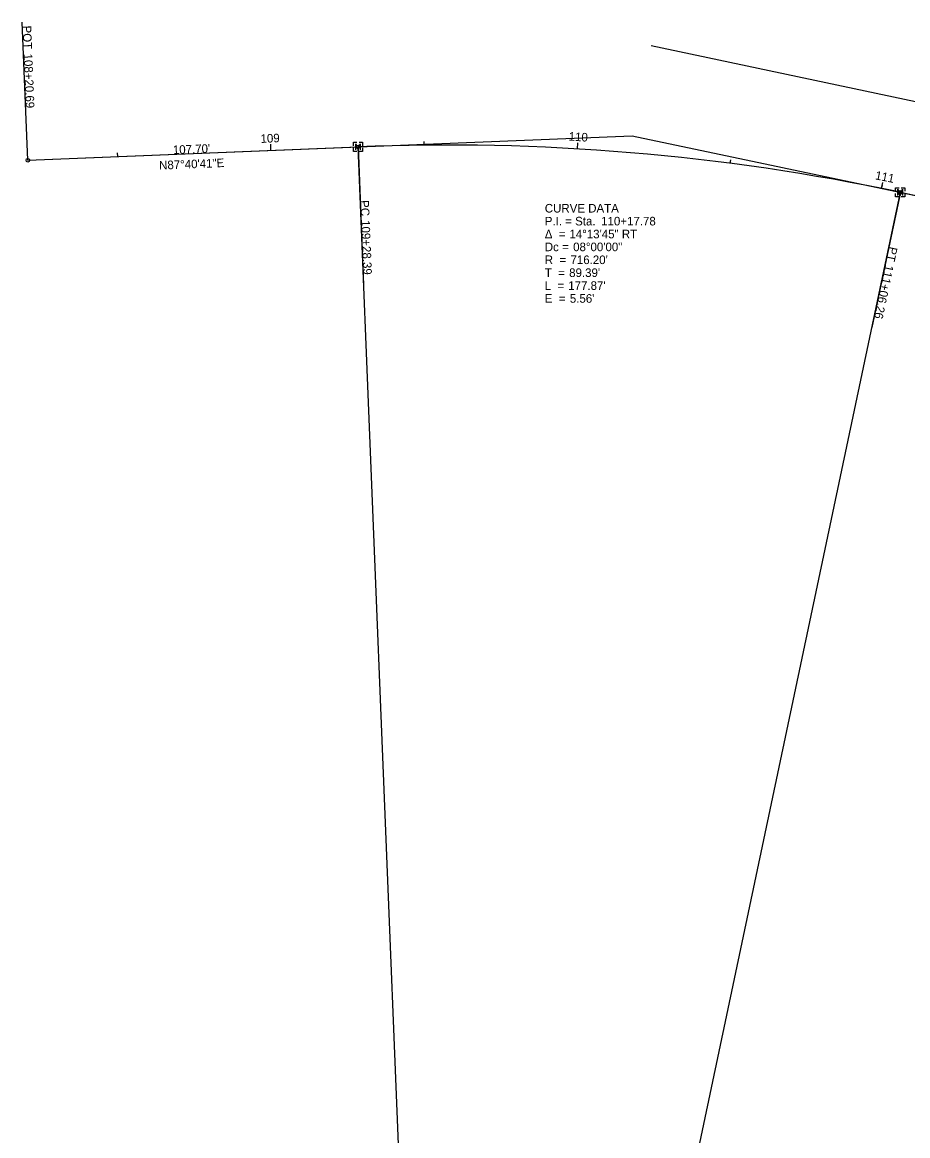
# Model space of a CAD drawing. Extents: x 2003596 to 2006888, y 571866 to 574416.
# Drawn here: x 2003595.8 to 2003884.4, y 572619.8 to 572982.7 of the extents above; entities that cross this region are included whole.
import ezdxf

# ---------------------------------------------------------------- set-up
doc = ezdxf.new("R2010")
doc.units = 0
for name, color, linetype in [('GE_X_Alignment', 7, 'Continuous'), ('GE_X_Alignment_1000_Bearings', 7, 'Continuous'), ('GE_X_Alignment_1000_Cardinal_Points', 7, 'Continuous'), ('GE_X_Alignment_1000_Curve_Data', 7, 'Continuous'), ('GE_X_Alignment_1000_Distances', 7, 'Continuous'), ('GE_X_Alignment_1000_Stations', 7, 'Continuous'), ('GE_X_Alignment_100_Bearings', 7, 'Continuous'), ('GE_X_Alignment_100_Cardinal_Points', 7, 'Continuous'), ('GE_X_Alignment_100_Curve_Data', 7, 'Continuous'), ('GE_X_Alignment_100_Distances', 7, 'Continuous'), ('GE_X_Alignment_100_Stations', 7, 'Continuous'), ('GE_X_Alignment_500_Bearings', 7, 'Continuous'), ('GE_X_Alignment_500_Cardinal_Points', 7, 'Continuous'), ('GE_X_Alignment_500_Curve_Data', 7, 'Continuous'), ('GE_X_Alignment_500_Distances', 7, 'Continuous'), ('GE_X_Alignment_500_Stations', 7, 'Continuous'), ('RW_X_Esmt_SH', 7, 'Continuous'), ('SC_Scratch1', 7, 'Continuous'), ('SV_X_Mon_Cells_Found', 7, 'Continuous'), ('SV_X_Random_Point', 7, 'Continuous')]:
    doc.layers.add(name, color=color, linetype=linetype)

msp = doc.modelspace()

# ---------------------------------------------------------------- linework, layer by layer
at = {"layer": 'GE_X_Alignment'}
for p, q in [((2003597.61, 572937.73), (2003705.22, 572942.09)), ((2003882.01, 572927.27), (2004086.95, 572884.06))]:
    msp.add_line(p, q, dxfattribs=at)
msp.add_arc((2003734.24, 572226.48), 716.2, 78.09264, 92.32181, dxfattribs=at)
at = {"layer": 'GE_X_Alignment_1000_Cardinal_Points'}
for p, q in [((2003597.61, 572937.73), (2003595.79, 572982.69)), ((2003705.22, 572942.09), (2003707.04, 572897.13)), ((2003882.01, 572927.27), (2003872.72, 572883.24))]:
    msp.add_line(p, q, dxfattribs=at)
for centre in [(2003705.22, 572942.09), (2003597.61, 572937.73), (2003882.01, 572927.27)]:
    msp.add_circle(centre, 0.6, dxfattribs=at)
at = {"layer": 'GE_X_Alignment_1000_Stations'}
msp.add_line((2003776.8, 572941.42), (2003776.92, 572943.41), dxfattribs=at)
at = {"layer": 'GE_X_Alignment_100_Cardinal_Points'}
for p, q in [((2003597.61, 572937.73), (2003595.79, 572982.69)), ((2003705.22, 572942.09), (2003707.04, 572897.13)), ((2003882.01, 572927.27), (2003872.72, 572883.24))]:
    msp.add_line(p, q, dxfattribs=at)
for centre in [(2003705.22, 572942.09), (2003597.61, 572937.73), (2003882.01, 572927.27)]:
    msp.add_circle(centre, 0.6, dxfattribs=at)
at = {"layer": 'GE_X_Alignment_100_Stations'}
for p, q in [((2003676.85, 572940.94), (2003676.77, 572942.94)), ((2003726.82, 572942.64), (2003726.81, 572943.84)), ((2003776.8, 572941.42), (2003776.92, 572943.41)), ((2003626.89, 572938.92), (2003626.85, 572940.12)), ((2003826.56, 572936.71), (2003826.72, 572937.9)), ((2003875.88, 572928.54), (2003876.28, 572930.5))]:
    msp.add_line(p, q, dxfattribs=at)
at = {"layer": 'GE_X_Alignment_500_Cardinal_Points'}
for p, q in [((2003597.61, 572937.73), (2003595.79, 572982.69)), ((2003705.22, 572942.09), (2003707.04, 572897.13)), ((2003882.01, 572927.27), (2003872.72, 572883.24))]:
    msp.add_line(p, q, dxfattribs=at)
for centre in [(2003705.22, 572942.09), (2003597.61, 572937.73), (2003882.01, 572927.27)]:
    msp.add_circle(centre, 0.6, dxfattribs=at)
at = {"layer": 'GE_X_Alignment_500_Stations'}
for p, q in [((2003776.8, 572941.42), (2003776.92, 572943.41)), ((2003676.85, 572940.94), (2003676.8, 572942.14)), ((2003875.88, 572928.54), (2003876.12, 572929.71))]:
    msp.add_line(p, q, dxfattribs=at)
at = {"layer": 'RW_X_Esmt_SH'}
msp.add_line((2003800.73, 572975.07), (2004225.49, 572885.5), dxfattribs=at)
at = {"layer": 'SC_Scratch1'}
for p, q in [((2003597.61, 572937.73), (2003794.54, 572945.72)), ((2003794.54, 572945.72), (2004215.36, 572856.98)), ((2003734.24, 572226.48), (2003705.22, 572942.09)), ((2003734.24, 572226.48), (2003882.01, 572927.27))]:
    msp.add_line(p, q, dxfattribs=at)
at = {"layer": 'SV_X_Mon_Cells_Found'}
for p, q in [((2003705.22, 572942.09), (2003705.22, 572942.09)), ((2003881.94, 572927.28), (2003881.94, 572927.28))]:
    msp.add_line(p, q, dxfattribs=at)
for points in [[(2003703.72, 572942.47), (2003703.72, 572943.6), (2003704.84, 572943.6)], [(2003704.48, 572941.09), (2003704.48, 572943.09), (2003705.22, 572941.09), (2003705.96, 572943.09), (2003705.96, 572941.09)], [(2003705.58, 572943.6), (2003706.72, 572943.6), (2003706.72, 572942.47)], [(2003704.84, 572940.59), (2003703.72, 572940.59), (2003703.72, 572941.72)], [(2003706.72, 572941.72), (2003706.72, 572940.59), (2003705.58, 572940.59)], [(2003880.44, 572927.66), (2003880.44, 572928.78), (2003881.56, 572928.78)], [(2003882.3, 572928.78), (2003883.44, 572928.78), (2003883.44, 572927.66)], [(2003881.56, 572925.78), (2003880.44, 572925.78), (2003880.44, 572926.9)], [(2003881.2, 572926.28), (2003881.2, 572928.28), (2003881.94, 572926.28), (2003882.68, 572928.28), (2003882.68, 572926.28)], [(2003883.44, 572926.9), (2003883.44, 572925.78), (2003882.3, 572925.78)]]:
    msp.add_lwpolyline(points, dxfattribs=at)
at = {"layer": 'SV_X_Random_Point'}
for p, q in [((2003881.34, 572926.6), (2003882.68, 572927.94)), ((2003881.34, 572927.94), (2003882.68, 572926.6))]:
    msp.add_line(p, q, dxfattribs=at)

# ---------------------------------------------------------------- texts
at = {"layer": 'GE_X_Alignment_1000_Bearings'}
msp.add_text('N87°40\'41"E', height=2.8, rotation=2.3218, dxfattribs=at).set_placement((2003640.44, 572934.66))
at = {"layer": 'GE_X_Alignment_1000_Cardinal_Points'}
for s, rotation, p in [('POT', 272.3218, (2003595.88, 572981.55)), ('108+20.69', 272.3218, (2003596.25, 572972.43)), ('PC', 272.3218, (2003705.97, 572924.66)), ('109+28.39', 272.3218, (2003706.24, 572918.14)), ('PT', 258.0925, (2003878.36, 572909.72)), ('111+06.26', 258.0925, (2003877.1, 572903.76))]:
    msp.add_text(s, height=2.8, rotation=rotation, dxfattribs=at).set_placement(p)
at = {"layer": 'GE_X_Alignment_1000_Curve_Data'}
for s, p in [('CURVE DATA', (2003766.1, 572920.68)), ('P.I. = Sta. ', (2003766.1, 572916.48)), ('110+17.78', (2003784.47, 572916.48)), ('Δ  = ', (2003766.1, 572912.28)), ('14°13\'45" RT', (2003774.13, 572912.28)), ('Dc = ', (2003766.1, 572908.08)), ('08°00\'00"', (2003775.34, 572908.08)), ('R  = ', (2003766.1, 572903.88)), ("716.20'", (2003774.47, 572903.88)), ('T  = ', (2003766.1, 572899.68)), ("89.39'", (2003774.04, 572899.68)), ('L  = ', (2003766.1, 572895.48)), ("177.87'", (2003773.75, 572895.48)), ('E  = ', (2003766.1, 572891.28)), ("5.56'", (2003774.26, 572891.28))]:
    msp.add_text(s, height=2.8, dxfattribs=at).set_placement(p)
at = {"layer": 'GE_X_Alignment_1000_Distances'}
msp.add_text("107.70'", height=2.8, rotation=2.3218, dxfattribs=at).set_placement((2003644.93, 572939.7))
at = {"layer": 'GE_X_Alignment_1000_Stations'}
msp.add_text('110', height=2.8, rotation=356.593, dxfattribs=at).set_placement((2003773.82, 572944.15))
at = {"layer": 'GE_X_Alignment_100_Bearings'}
msp.add_text('N87°40\'41"E', height=2.8, rotation=2.3218, dxfattribs=at).set_placement((2003640.44, 572934.66))
at = {"layer": 'GE_X_Alignment_100_Cardinal_Points'}
for s, rotation, p in [('POT', 272.3218, (2003595.88, 572981.55)), ('108+20.69', 272.3218, (2003596.25, 572972.43)), ('PC', 272.3218, (2003705.97, 572924.66)), ('109+28.39', 272.3218, (2003706.24, 572918.14)), ('PT', 258.0925, (2003878.36, 572909.72)), ('111+06.26', 258.0925, (2003877.1, 572903.76))]:
    msp.add_text(s, height=2.8, rotation=rotation, dxfattribs=at).set_placement(p)
at = {"layer": 'GE_X_Alignment_100_Curve_Data'}
for s, p in [('CURVE DATA', (2003766.1, 572920.68)), ('P.I. = Sta. ', (2003766.1, 572916.48)), ('110+17.78', (2003784.47, 572916.48)), ('Δ  = ', (2003766.1, 572912.28)), ('14°13\'45" RT', (2003774.13, 572912.28)), ('Dc = ', (2003766.1, 572908.08)), ('08°00\'00"', (2003775.34, 572908.08)), ('R  = ', (2003766.1, 572903.88)), ("716.20'", (2003774.47, 572903.88)), ('T  = ', (2003766.1, 572899.68)), ("89.39'", (2003774.04, 572899.68)), ('L  = ', (2003766.1, 572895.48)), ("177.87'", (2003773.75, 572895.48)), ('E  = ', (2003766.1, 572891.28)), ("5.56'", (2003774.26, 572891.28))]:
    msp.add_text(s, height=2.8, dxfattribs=at).set_placement(p)
at = {"layer": 'GE_X_Alignment_100_Distances'}
msp.add_text("107.70'", height=2.8, rotation=2.3218, dxfattribs=at).set_placement((2003644.93, 572939.7))
at = {"layer": 'GE_X_Alignment_100_Stations'}
for s, rotation, p in [('110', 356.593, (2003773.82, 572944.15)), ('109', 2.3218, (2003673.5, 572943.36)), ('111', 348.5931, (2003873.61, 572931.54))]:
    msp.add_text(s, height=2.8, rotation=rotation, dxfattribs=at).set_placement(p)
at = {"layer": 'GE_X_Alignment_500_Bearings'}
msp.add_text('N87°40\'41"E', height=2.8, rotation=2.3218, dxfattribs=at).set_placement((2003640.44, 572934.66))
at = {"layer": 'GE_X_Alignment_500_Cardinal_Points'}
for s, rotation, p in [('POT', 272.3218, (2003595.88, 572981.55)), ('108+20.69', 272.3218, (2003596.25, 572972.43)), ('PC', 272.3218, (2003705.97, 572924.66)), ('109+28.39', 272.3218, (2003706.24, 572918.14)), ('PT', 258.0925, (2003878.36, 572909.72)), ('111+06.26', 258.0925, (2003877.1, 572903.76))]:
    msp.add_text(s, height=2.8, rotation=rotation, dxfattribs=at).set_placement(p)
at = {"layer": 'GE_X_Alignment_500_Curve_Data'}
for s, p in [('CURVE DATA', (2003766.1, 572920.68)), ('P.I. = Sta. ', (2003766.1, 572916.48)), ('110+17.78', (2003784.47, 572916.48)), ('Δ  = ', (2003766.1, 572912.28)), ('14°13\'45" RT', (2003774.13, 572912.28)), ('Dc = ', (2003766.1, 572908.08)), ('08°00\'00"', (2003775.34, 572908.08)), ('R  = ', (2003766.1, 572903.88)), ("716.20'", (2003774.47, 572903.88)), ('T  = ', (2003766.1, 572899.68)), ("89.39'", (2003774.04, 572899.68)), ('L  = ', (2003766.1, 572895.48)), ("177.87'", (2003773.75, 572895.48)), ('E  = ', (2003766.1, 572891.28)), ("5.56'", (2003774.26, 572891.28))]:
    msp.add_text(s, height=2.8, dxfattribs=at).set_placement(p)
at = {"layer": 'GE_X_Alignment_500_Distances'}
msp.add_text("107.70'", height=2.8, rotation=2.3218, dxfattribs=at).set_placement((2003644.93, 572939.7))
at = {"layer": 'GE_X_Alignment_500_Stations'}
msp.add_text('110', height=2.8, rotation=356.593, dxfattribs=at).set_placement((2003773.82, 572944.15))

doc.saveas('drawing.dxf')
